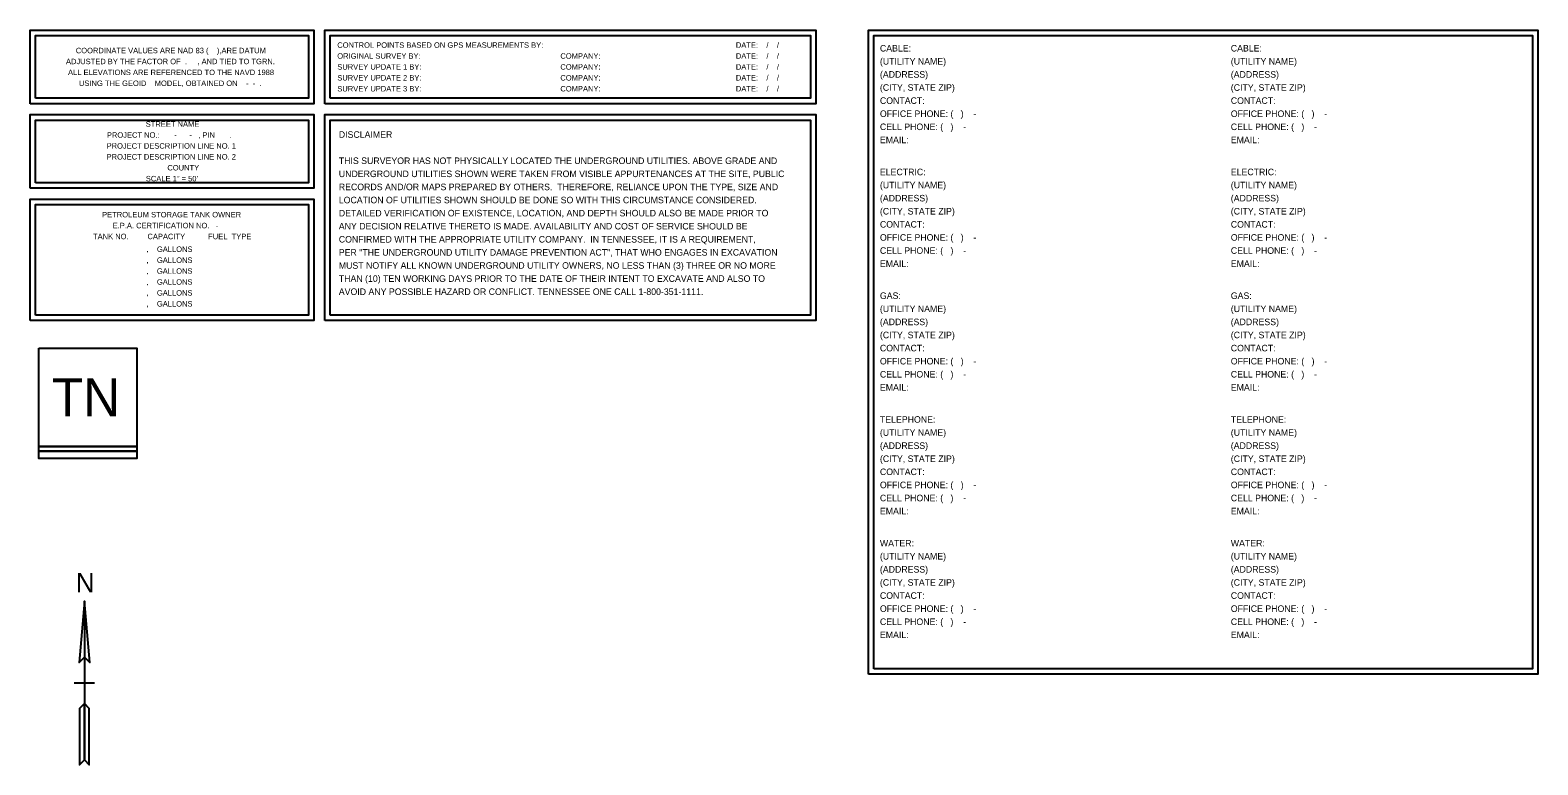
# Model space of a CAD drawing. Extents: x 514 to 1896, y 344 to 1017.
import ezdxf

# ---------------------------------------------------------------- set-up
doc = ezdxf.new("R2010")
doc.units = 0
for name, color, linetype in [('_CIVIL_CONSTRUCTION', 7, 'Continuous'), ('DES - ROW - Easement Linework', 7, 'Continuous'), ('DES - TRAN - Roadside Barriers - Guardrail', 7, 'Continuous')]:
    doc.layers.add(name, color=color, linetype=linetype)

msp = doc.modelspace()

# ---------------------------------------------------------------- linework, layer by layer
at = {"layer": '_CIVIL_CONSTRUCTION'}
for points in [[(514.3, 949.9), (514.3, 1017.3), (774.3, 1017.3), (774.3, 949.9)], [(519.3, 954.9), (519.3, 1012.3), (769.3, 1012.3), (769.3, 954.9)], [(784.3, 949.9), (784.3, 1017.3), (1234.3, 1017.3), (1234.3, 949.9)], [(789.3, 954.9), (789.3, 1012.3), (1229.3, 1012.3), (1229.3, 954.9)]]:
    msp.add_lwpolyline(points, close=True, dxfattribs=at)
at = {"layer": 'DES - ROW - Easement Linework'}
for p, q in [((564, 418.9), (554.5, 418.9)), ((573.4, 418.9), (564, 418.9))]:
    msp.add_line(p, q, dxfattribs=at)
for points in [[(514.3, 872.5), (514.3, 939.9), (774.3, 939.9), (774.3, 872.5)], [(519.3, 877.5), (519.3, 934.9), (769.3, 934.9), (769.3, 877.5)], [(514.3, 751.1), (514.3, 862.5), (774.3, 862.5), (774.3, 751.1)], [(519.3, 756.1), (519.3, 857.5), (769.3, 857.5), (769.3, 756.1)], [(522.1, 725.8), (612.1, 725.8), (612.1, 635.8), (522.1, 635.8)], [(522.1, 725.8), (612.1, 725.8), (612.1, 635.8), (522.1, 635.8)], [(522.1, 635.8), (612.1, 635.8), (612.1, 631.3), (522.1, 631.3)], [(522.1, 635.8), (612.1, 635.8), (612.1, 631.3), (522.1, 631.3)], [(522.1, 631.3), (612.1, 631.3), (612.1, 624.6), (522.1, 624.6)], [(522.1, 631.3), (612.1, 631.3), (612.1, 624.6), (522.1, 624.6)], [(564, 442.5), (568.9, 437.6), (564, 493.9)], [(559.4, 343.9), (564, 348.5), (564, 400.2), (559.4, 395.7)]]:
    msp.add_lwpolyline(points, close=True, dxfattribs=at)
msp.add_lwpolyline([(564, 493.9), (559.1, 437.6), (564, 442.5), (568.9, 437.6), (564, 493.9), (564, 348.5), (568.5, 343.9), (568.5, 395.7), (564, 400.2), (559.4, 395.7), (559.4, 343.9), (564, 348.5)], dxfattribs=at)
at = {"layer": 'DES - TRAN - Roadside Barriers - Guardrail'}
for points in [[(1282.4, 426.9), (1282.4, 1017.3), (1895.7, 1017.3), (1895.7, 426.9)], [(1287.4, 431.9), (1287.4, 1012.3), (1890.7, 1012.3), (1890.7, 431.9)], [(784.3, 751.1), (784.3, 939.9), (1234.3, 939.9), (1234.3, 751.1)], [(789.3, 756.1), (789.3, 934.9), (1229.3, 934.9), (1229.3, 756.1)]]:
    msp.add_lwpolyline(points, close=True, dxfattribs=at)

# ---------------------------------------------------------------- texts
at = {"layer": '_CIVIL_CONSTRUCTION'}
for s, p in [('COORDINATE VALUES ARE NAD 83 (    ),ARE DATUM', (556.1, 996.1)), ('ORIGINAL SURVEY BY:                               ', (795.7, 991.1)), ('CONTROL POINTS BASED ON GPS MEASUREMENTS BY:                                            ', (795.7, 1001.1)), ('COMPANY:                               ', (1000.1, 991.1)), ('DATE:    /    /   ', (1160.9, 1001.1)), ('DATE:    /    /    ', (1160.9, 991.1)), ('ADJUSTED BY THE FACTOR OF  .     , AND TIED TO TGRN. ', (547.1, 986.1)), ('ALL ELEVATIONS ARE REFERENCED TO THE NAVD 1988', (549, 976.1)), ('SURVEY UPDATE 1 BY:                               ', (795.7, 981.1)), ('COMPANY:                               ', (1000.1, 981.1)), ('DATE:    /    /     ', (1160.9, 981.1)), ('USING THE GEOID    MODEL, OBTAINED ON    -  -  .', (559, 966.1)), ('SURVEY UPDATE 2 BY:                               ', (795.7, 971.1)), ('COMPANY:                               ', (1000.1, 971.1)), ('DATE:    /    /     ', (1160.9, 971.1)), ('SURVEY UPDATE 3 BY:                               ', (795.7, 961.1)), ('COMPANY:                               ', (1000.1, 961.1)), ('DATE:    /    /    ', (1160.9, 961.1))]:
    msp.add_text(s, height=5, dxfattribs=at).set_placement(p)
at = {"layer": 'DES - ROW - Easement Linework'}
for s, height, p in [('            STREET NAME           ', 5, (597.2, 928.7)), ('  PROJECT DESCRIPTION LINE NO. 1  ', 5, (580.5, 908.7)), ('PROJECT NO.:       -      -   , PIN       .  ', 5, (584.6, 918.7)), ('  PROJECT DESCRIPTION LINE NO. 2  ', 5, (580.5, 898.7)), ('           COUNTY', 5, (618.9, 888.7)), ('SCALE 1" = 50\'', 5, (620.3, 878.7)), (' PETROLEUM STORAGE TANK OWNER ', 5, (578.3, 845.7)), ('TANK NO.         CAPACITY           FUEL  TYPE', 5, (571.9, 825.7)), ('E.P.A. CERTIFICATION NO.   -      ', 5, (589.9, 835.7)), ('  ,    GALLONS', 5, (617, 814)), ('   ,    GALLONS', 5, (615.1, 804)), ('  ,    GALLONS', 5, (617, 794)), ('  ,    GALLONS', 5, (617, 784)), ('  ,    GALLONS', 5, (617, 774)), ('  ,    GALLONS', 5, (617, 764)), ('TN', 35, (534.3, 663.3)), ('N', 17.7, (556.2, 502))]:
    msp.add_text(s, height=height, dxfattribs=at).set_placement(p)
at = {"layer": 'DES - TRAN - Roadside Barriers - Guardrail'}
for s, p in [('CABLE:', (1292.9, 997.7)), ('CABLE:', (1614.4, 997.7)), ('(UTILITY NAME)                                    ', (1292.9, 985.7)), ('(UTILITY NAME)                                    ', (1614.4, 985.7)), ('(ADDRESS)                                               ', (1292.9, 973.7)), ('(CITY, STATE ZIP)                                 ', (1292.9, 961.7)), ('(ADDRESS)                                               ', (1614.4, 973.7)), ('(CITY, STATE ZIP)                                 ', (1614.4, 961.7)), ('CONTACT:                                                   ', (1292.9, 949.7)), ('CONTACT:                                                   ', (1614.4, 949.7)), ('OFFICE PHONE: (   )    -    ', (1292.9, 937.7)), ('OFFICE PHONE: (   )    -    ', (1614.4, 937.7)), ('CELL PHONE: (   )    -    ', (1292.9, 925.7)), ('CELL PHONE: (   )    -    ', (1614.4, 925.7)), ('DISCLAIMER', (797.1, 918.6)), ('EMAIL:                                                    ', (1292.9, 913.7)), ('EMAIL:                                                    ', (1614.4, 913.7)), ('THIS SURVEYOR HAS NOT PHYSICALLY LOCATED THE UNDERGROUND UTILITIES. ABOVE GRADE AND ', (797.1, 894.6)), ('UNDERGROUND UTILITIES SHOWN WERE TAKEN FROM VISIBLE APPURTENANCES AT THE SITE, PUBLIC ', (797.1, 882.6)), ('ELECTRIC:', (1292.9, 884.3)), ('ELECTRIC:', (1614.4, 884.3)), ('RECORDS AND/OR MAPS PREPARED BY OTHERS.  THEREFORE, RELIANCE UPON THE TYPE, SIZE AND ', (797.1, 870.6)), ('(UTILITY NAME)                                    ', (1292.9, 872.3)), ('(UTILITY NAME)                                    ', (1614.4, 872.3)), ('LOCATION OF UTILITIES SHOWN SHOULD BE DONE SO WITH THIS CIRCUMSTANCE CONSIDERED.', (797.1, 858.6)), ('(ADDRESS)                                         ', (1292.9, 860.3)), ('(ADDRESS)                                         ', (1614.4, 860.3)), ('DETAILED VERIFICATION OF EXISTENCE, LOCATION, AND DEPTH SHOULD ALSO BE MADE PRIOR TO ', (797.1, 846.6)), ('(CITY, STATE ZIP)                                 ', (1292.9, 848.3)), ('(CITY, STATE ZIP)                                 ', (1614.4, 848.3)), ('ANY DECISION RELATIVE THERETO IS MADE. AVAILABILITY AND COST OF SERVICE SHOULD BE ', (797.1, 834.6)), ('CONTACT:                                                   ', (1292.9, 836.3)), ('OFFICE PHONE: (   )    -    ', (1292.9, 824.3)), ('CONTACT:                                                   ', (1614.4, 836.3)), ('OFFICE PHONE: (   )    -    ', (1614.4, 824.3)), ('CONFIRMED WITH THE APPROPRIATE UTILITY COMPANY.  IN TENNESSEE, IT IS A REQUIREMENT, ', (797.1, 822.6)), ('PER "THE UNDERGROUND UTILITY DAMAGE PREVENTION ACT", THAT WHO ENGAGES IN EXCAVATION ', (797.1, 810.6)), ('CELL PHONE: (   )    -    ', (1292.9, 812.3)), ('CELL PHONE: (   )    -    ', (1614.4, 812.3)), ('MUST NOTIFY ALL KNOWN UNDERGROUND UTILITY OWNERS, NO LESS THAN (3) THREE OR NO MORE ', (797.1, 798.6)), ('EMAIL:                                                    ', (1292.9, 800.3)), ('EMAIL:                                                    ', (1614.4, 800.3)), ('THAN (10) TEN WORKING DAYS PRIOR TO THE DATE OF THEIR INTENT TO EXCAVATE AND ALSO TO ', (797.1, 786.6)), ('AVOID ANY POSSIBLE HAZARD OR CONFLICT. TENNESSEE ONE CALL 1-800-351-1111.', (797.1, 774.6)), ('GAS:', (1292.9, 770.9)), ('GAS:', (1614.4, 770.9)), ('(UTILITY NAME)                                    ', (1292.9, 758.9)), ('(UTILITY NAME)                                    ', (1614.4, 758.9)), ('(ADDRESS)                                         ', (1292.9, 746.9)), ('(ADDRESS)                                         ', (1614.4, 746.9)), ('(CITY, STATE ZIP)                                 ', (1292.9, 734.9)), ('(CITY, STATE ZIP)                                 ', (1614.4, 734.9)), ('CONTACT:                                                   ', (1292.9, 722.9)), ('CONTACT:                                                   ', (1614.4, 722.9)), ('OFFICE PHONE: (   )    -    ', (1292.9, 710.9)), ('CELL PHONE: (   )    -    ', (1292.9, 698.9)), ('OFFICE PHONE: (   )    -    ', (1614.4, 710.9)), ('CELL PHONE: (   )    -    ', (1614.4, 698.9)), ('EMAIL:                                                    ', (1292.9, 686.9)), ('EMAIL:                                                    ', (1614.4, 686.9)), ('TELEPHONE:', (1292.9, 657.5)), ('TELEPHONE:', (1614.4, 657.5)), ('(UTILITY NAME)                                    ', (1292.9, 645.5)), ('(UTILITY NAME)                                    ', (1614.4, 645.5)), ('(ADDRESS)                                         ', (1292.9, 633.5)), ('(ADDRESS)                                         ', (1614.4, 633.5)), ('(CITY, STATE ZIP)                                 ', (1292.9, 621.5)), ('(CITY, STATE ZIP)                                 ', (1614.4, 621.5)), ('CONTACT:                                                   ', (1292.9, 609.5)), ('CONTACT:                                                   ', (1614.4, 609.5)), ('OFFICE PHONE: (   )    -    ', (1292.9, 597.5)), ('OFFICE PHONE: (   )    -    ', (1614.4, 597.5)), ('CELL PHONE: (   )    -    ', (1292.9, 585.5)), ('CELL PHONE: (   )    -    ', (1614.4, 585.5)), ('EMAIL:                                                    ', (1292.9, 573.5)), ('EMAIL:                                                    ', (1614.4, 573.5)), ('WATER:', (1292.9, 544.1)), ('WATER:', (1614.4, 544.1)), ('(UTILITY NAME)                                    ', (1292.9, 532.1)), ('(ADDRESS)                                         ', (1292.9, 520.1)), ('(UTILITY NAME)                                    ', (1614.4, 532.1)), ('(ADDRESS)                                         ', (1614.4, 520.1)), ('(CITY, STATE ZIP)                                 ', (1292.9, 508.1)), ('(CITY, STATE ZIP)                                 ', (1614.4, 508.1)), ('CONTACT:                                                   ', (1292.9, 496.1)), ('CONTACT:                                                   ', (1614.4, 496.1)), ('OFFICE PHONE: (   )    -    ', (1292.9, 484.1)), ('OFFICE PHONE: (   )    -    ', (1614.4, 484.1)), ('CELL PHONE: (   )    -    ', (1292.9, 472.1)), ('CELL PHONE: (   )    -    ', (1614.4, 472.1)), ('EMAIL:                                                    ', (1292.9, 460.1)), ('EMAIL:                                                    ', (1614.4, 460.1))]:
    msp.add_text(s, height=6, dxfattribs=at).set_placement(p)

doc.saveas('drawing.dxf')
